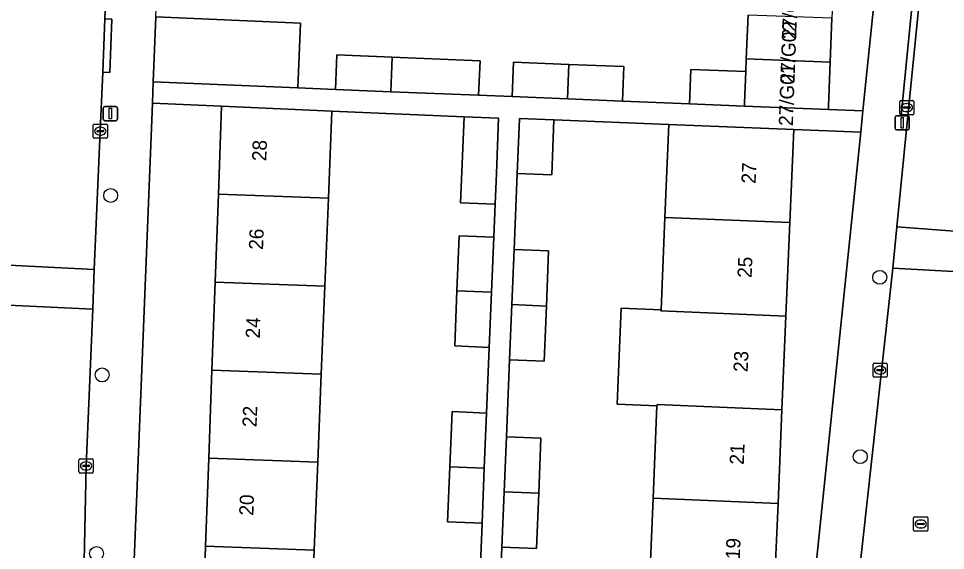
# Model space of a CAD drawing. Extents: x 161354 to 162026, y 386504 to 387460.
# Drawn here: x 161732.9 to 161798.1, y 386751.9 to 386789.3 of the extents above; entities that cross this region are included whole.
import ezdxf

# ---------------------------------------------------------------- set-up
doc = ezdxf.new("R2010")
doc.units = 0
for name, color, linetype in [('IMGEO_Boom', 7, 'Continuous'), ('IMGEO_Erf', 7, 'Continuous'), ('IMGEO_Kolk', 7, 'Continuous'), ('IMGEO_Lichtmast', 7, 'Continuous'), ('IMGEO_Pand', 7, 'Continuous'), ('IMGEO_Pand_nummerreeks', 7, 'Continuous'), ('IMGEO_Rijbaan_lokaal_open', 7, 'Continuous'), ('IMGEO_Rioolput', 7, 'Continuous'), ('IMGEO_Voetpad_open', 7, 'Continuous')]:
    doc.layers.add(name, color=color, linetype=linetype)

msp = doc.modelspace()

# ---------------------------------------------------------------- linework, layer by layer
at = {"layer": 'IMGEO_Boom'}
for centre in [(161739.398, 386776.816), (161793.481, 386771.055), (161738.8, 386764.195), (161792.114, 386758.447), (161738.405, 386751.637)]:
    msp.add_circle(centre, 0.489, dxfattribs=at)
at = {"layer": 'IMGEO_Erf'}
for points in [[(161765.792, 386796.634), (161759.615, 386796.878), (161753.439, 386797.123), (161752.087, 386797.176), (161747.09, 386797.374), (161747.4, 386805.213), (161753.749, 386804.962), (161759.925, 386804.718), (161766.102, 386804.474), (161772.278, 386804.229), (161778.454, 386803.985), (161784.804, 386803.734), (161784.607, 386798.749), (161790.487, 386798.516), (161790.365, 386795.433), (161790.243, 386792.35), (161790.122, 386789.267), (161790, 386786.184), (161789.878, 386783.101), (161789.868, 386782.851), (161792.296, 386782.754), (161794.675, 386805.874)], [(161742.569, 386789.374), (161752.738, 386788.938), (161752.567, 386784.376), (161755.212, 386784.268), (161755.312, 386786.696), (161759.189, 386786.537), (161765.376, 386786.284), (161765.276, 386783.856), (161767.635, 386783.76), (161767.735, 386786.188), (161771.611, 386786.029), (161775.488, 386785.871), (161775.389, 386783.443), (161780.109, 386783.25), (161780.209, 386785.678), (161784.064, 386785.52), (161784.099, 386786.417), (161784.221, 386789.5)], [(161745.992, 386750), (161746.071, 386752.161), (161746.296, 386758.348), (161746.521, 386764.534), (161746.746, 386770.721), (161746.971, 386776.908), (161747.196, 386783.084), (161742.334, 386783.293), (161741.004, 386750)], [(161765.324, 386749.126), (161765.514, 386753.763), (161763.086, 386753.862), (161763.244, 386757.739), (161763.403, 386761.616), (161765.831, 386761.516), (161766.02, 386766.133), (161763.592, 386766.233), (161763.751, 386770.109), (161763.91, 386773.986), (161766.338, 386773.887), (161766.433, 386776.199), (161764.005, 386776.287), (161764.252, 386782.351), (161754.954, 386782.751), (161754.707, 386776.626), (161754.457, 386770.439), (161754.207, 386764.253), (161753.957, 386758.068), (161753.707, 386751.882), (161753.631, 386750)], [(161777.312, 386750), (161777.545, 386755.532), (161777.817, 386762.029), (161775.025, 386762.147), (161775.309, 386768.895), (161778.102, 386768.778), (161778.375, 386775.275), (161778.649, 386781.805), (161770.573, 386782.134), (161770.414, 386778.257), (161767.986, 386778.357), (161767.768, 386773.013), (161770.196, 386772.914), (161770.038, 386769.037), (161769.879, 386765.16), (161767.451, 386765.259), (161767.23, 386759.85), (161769.658, 386759.751), (161769.5, 386755.874), (161769.341, 386751.997), (161766.913, 386752.096), (161766.692, 386746.687)]]:
    msp.add_lwpolyline(points, dxfattribs=at)
msp.add_lwpolyline([(161792.142, 386781.256), (161787.434, 386781.448), (161787.159, 386774.905), (161786.882, 386768.324), (161786.605, 386761.743), (161786.328, 386755.162), (161786.111, 386750), (161786.051, 386748.58), (161785.774, 386741.999), (161785.497, 386735.418), (161785.213, 386728.667), (161786.714, 386728.514), (161788.925, 386750)], close=True, dxfattribs=at)
at = {"layer": 'IMGEO_Kolk'}
for p, q in [((161794.887, 386782.566), (161794.887, 386783.418)), ((161794.962, 386783.492), (161795.814, 386783.492)), ((161795.888, 386783.418), (161795.888, 386782.566)), ((161795.146, 386782.986), (161795.146, 386782.998)), ((161795.584, 386782.949), (161795.186, 386782.949)), ((161795.189, 386783.035), (161795.587, 386783.035)), ((161795.398, 386782.712), (161795.373, 386782.712)), ((161795.375, 386783.272), (161795.4, 386783.272)), ((161795.63, 386782.998), (161795.63, 386782.986)), ((161795.814, 386782.492), (161794.962, 386782.492)), ((161738.169, 386780.908), (161738.169, 386781.76)), ((161738.244, 386781.834), (161739.096, 386781.834)), ((161738.471, 386781.377), (161738.869, 386781.377)), ((161738.657, 386781.614), (161738.682, 386781.614)), ((161739.17, 386781.76), (161739.17, 386780.908)), ((161739.096, 386780.834), (161738.244, 386780.834)), ((161738.428, 386781.328), (161738.428, 386781.34)), ((161738.866, 386781.291), (161738.468, 386781.291)), ((161738.68, 386781.054), (161738.655, 386781.054)), ((161738.912, 386781.34), (161738.912, 386781.328)), ((161793.011, 386764.107), (161793.011, 386764.959)), ((161793.086, 386765.033), (161793.938, 386765.033)), ((161793.27, 386764.527), (161793.27, 386764.539)), ((161793.708, 386764.49), (161793.31, 386764.49)), ((161793.313, 386764.576), (161793.711, 386764.576)), ((161793.499, 386764.813), (161793.524, 386764.813)), ((161793.754, 386764.539), (161793.754, 386764.527)), ((161794.012, 386764.959), (161794.012, 386764.107)), ((161793.938, 386764.033), (161793.086, 386764.033)), ((161793.522, 386764.253), (161793.497, 386764.253)), ((161737.168, 386757.374), (161737.168, 386758.226)), ((161737.243, 386758.3), (161738.095, 386758.3)), ((161737.656, 386758.08), (161737.681, 386758.08)), ((161738.169, 386758.226), (161738.169, 386757.374)), ((161738.095, 386757.3), (161737.243, 386757.3)), ((161737.427, 386757.794), (161737.427, 386757.806)), ((161737.865, 386757.757), (161737.467, 386757.757)), ((161737.47, 386757.843), (161737.868, 386757.843)), ((161737.679, 386757.52), (161737.654, 386757.52)), ((161737.911, 386757.806), (161737.911, 386757.794))]:
    msp.add_line(p, q, dxfattribs=at)
for points in [[(161794.887, 386782.566), (161794.887, 386783.418)], [(161794.962, 386783.492), (161795.814, 386783.492)], [(161795.888, 386783.418), (161795.888, 386782.566)], [(161795.814, 386782.492), (161794.962, 386782.492)], [(161738.169, 386780.908), (161738.169, 386781.76)], [(161738.244, 386781.834), (161739.096, 386781.834)], [(161739.17, 386781.76), (161739.17, 386780.908)], [(161739.096, 386780.834), (161738.244, 386780.834)], [(161793.011, 386764.107), (161793.011, 386764.959)], [(161793.086, 386765.033), (161793.938, 386765.033)], [(161794.012, 386764.959), (161794.012, 386764.107)], [(161793.938, 386764.033), (161793.086, 386764.033)], [(161737.168, 386757.374), (161737.168, 386758.226)], [(161737.243, 386758.3), (161738.095, 386758.3)], [(161738.169, 386758.226), (161738.169, 386757.374)], [(161738.095, 386757.3), (161737.243, 386757.3)]]:
    msp.add_lwpolyline(points, dxfattribs=at)
for centre, radius, start, end in [((161794.964, 386783.416), 0.0765, 91.55205, 178.44795), ((161794.964, 386783.416), 0.0765, 91.55205, 178.44795), ((161795.812, 386783.416), 0.0765, 1.55205, 88.44795), ((161795.812, 386783.416), 0.0765, 1.55205, 88.44795), ((161795.186, 386782.995), 0.0403, 85.87752, 175.75265), ((161795.183, 386782.985), 0.0366, 178.93798, 274.71019), ((161795.587, 386782.992), 0.043, 264.86636, 352.45326), ((161795.591, 386782.997), 0.0386, 1.73085, 96.63898), ((161794.964, 386782.568), 0.0765, 181.55205, 268.44795), ((161794.964, 386782.568), 0.0765, 181.55205, 268.44795), ((161795.812, 386782.568), 0.0765, 271.55205, 358.44795), ((161795.812, 386782.568), 0.0765, 271.55205, 358.44795), ((161738.246, 386781.758), 0.0765, 91.55205, 178.44795), ((161738.246, 386781.758), 0.0765, 91.55205, 178.44795), ((161738.468, 386781.337), 0.0403, 85.87752, 175.75265), ((161738.873, 386781.339), 0.0386, 1.73085, 96.63898), ((161739.094, 386781.758), 0.0765, 1.55205, 88.44795), ((161739.094, 386781.758), 0.0765, 1.55205, 88.44795), ((161738.246, 386780.91), 0.0765, 181.55205, 268.44795), ((161738.246, 386780.91), 0.0765, 181.55205, 268.44795), ((161738.465, 386781.327), 0.0366, 178.93798, 274.71019), ((161738.869, 386781.334), 0.043, 264.86636, 352.45326), ((161739.094, 386780.91), 0.0765, 271.55205, 358.44795), ((161739.094, 386780.91), 0.0765, 271.55205, 358.44795), ((161793.088, 386764.957), 0.0765, 91.55205, 178.44795), ((161793.088, 386764.957), 0.0765, 91.55205, 178.44795), ((161793.31, 386764.536), 0.0403, 85.87752, 175.75265), ((161793.307, 386764.526), 0.0366, 178.93798, 274.71019), ((161793.711, 386764.533), 0.043, 264.86636, 352.45326), ((161793.715, 386764.538), 0.0386, 1.73085, 96.63898), ((161793.936, 386764.957), 0.0765, 1.55205, 88.44795), ((161793.936, 386764.957), 0.0765, 1.55205, 88.44795), ((161793.088, 386764.109), 0.0765, 181.55205, 268.44795), ((161793.088, 386764.109), 0.0765, 181.55205, 268.44795), ((161793.936, 386764.109), 0.0765, 271.55205, 358.44795), ((161793.936, 386764.109), 0.0765, 271.55205, 358.44795), ((161737.245, 386758.224), 0.0765, 91.55205, 178.44795), ((161737.245, 386758.224), 0.0765, 91.55205, 178.44795), ((161738.093, 386758.224), 0.0765, 1.55205, 88.44795), ((161738.093, 386758.224), 0.0765, 1.55205, 88.44795), ((161737.245, 386757.376), 0.0765, 181.55205, 268.44795), ((161737.245, 386757.376), 0.0765, 181.55205, 268.44795), ((161737.467, 386757.803), 0.0403, 85.87752, 175.75265), ((161737.464, 386757.793), 0.0366, 178.93798, 274.71019), ((161737.868, 386757.8), 0.043, 264.86636, 352.45326), ((161737.872, 386757.805), 0.0386, 1.73085, 96.63898), ((161738.093, 386757.376), 0.0765, 271.55205, 358.44795), ((161738.093, 386757.376), 0.0765, 271.55205, 358.44795)]:
    msp.add_arc(centre, radius, start, end, dxfattribs=at)
for centre, major_axis, ratio, start_param, end_param in [((161795.374, 386782.992), (-0.387, 0.002), 0.722429, 4.712389, 7.853982), ((161795.399, 386782.992), (-0.39, 0.002), 0.717154, 1.570796, 4.712389), ((161738.656, 386781.334), (-0.387, 0.002), 0.722429, 4.712389, 7.853982), ((161738.681, 386781.334), (-0.39, 0.002), 0.717154, 1.570796, 4.712389), ((161793.498, 386764.533), (-0.387, 0.002), 0.722429, 4.712389, 7.853982), ((161793.523, 386764.533), (-0.39, 0.002), 0.717154, 1.570796, 4.712389), ((161737.655, 386757.8), (-0.387, 0.002), 0.722429, 4.712389, 7.853982), ((161737.68, 386757.8), (-0.39, 0.002), 0.717154, 1.570796, 4.712389)]:
    msp.add_ellipse(centre, major_axis=major_axis, ratio=ratio, start_param=start_param, end_param=end_param, dxfattribs=at)
at = {"layer": 'IMGEO_Lichtmast'}
for p, q in [((161738.875, 386782.168), (161738.875, 386782.968)), ((161738.875, 386782.968), (161738.875, 386782.168)), ((161738.975, 386783.068), (161739.765, 386783.068)), ((161739.765, 386783.068), (161738.975, 386783.068)), ((161739.865, 386782.968), (161739.865, 386782.168)), ((161739.865, 386782.168), (161739.865, 386782.968)), ((161739.765, 386782.068), (161738.975, 386782.068)), ((161738.975, 386782.068), (161739.765, 386782.068)), ((161794.565, 386781.521), (161794.565, 386782.321)), ((161794.565, 386782.321), (161794.565, 386781.521)), ((161794.665, 386782.421), (161795.455, 386782.421)), ((161795.455, 386782.421), (161794.665, 386782.421)), ((161795.555, 386782.321), (161795.555, 386781.521)), ((161795.555, 386781.521), (161795.555, 386782.321)), ((161795.455, 386781.421), (161794.665, 386781.421)), ((161794.665, 386781.421), (161795.455, 386781.421))]:
    msp.add_line(p, q, dxfattribs=at)
for points in [[(161739.295, 386782.943), (161739.445, 386782.943), (161739.445, 386782.193), (161739.295, 386782.193), (161739.295, 386782.943)], [(161794.985, 386782.296), (161795.135, 386782.296), (161795.135, 386781.546), (161794.985, 386781.546), (161794.985, 386782.296)]]:
    msp.add_lwpolyline(points, dxfattribs=at)
for centre, start, end in [((161738.975, 386782.968), 90, 180), ((161738.975, 386782.968), 90, 180), ((161739.765, 386782.968), 0, 90), ((161739.765, 386782.968), 360, 90), ((161738.975, 386782.168), 180, 270), ((161738.975, 386782.168), 180, 270), ((161739.765, 386782.168), 270, 0), ((161739.765, 386782.168), 270, 0), ((161794.665, 386782.321), 90, 180), ((161794.665, 386782.321), 90, 180), ((161795.455, 386782.321), 0, 90), ((161795.455, 386782.321), 360, 90), ((161794.665, 386781.521), 180, 270), ((161794.665, 386781.521), 180, 270), ((161795.455, 386781.521), 270, 0), ((161795.455, 386781.521), 270, 0)]:
    msp.add_arc(centre, 0.1, start, end, dxfattribs=at)
at = {"layer": 'IMGEO_Pand'}
for points in [[(161752.738, 386788.938), (161742.569, 386789.374), (161742.388, 386784.792), (161752.567, 386784.376)], [(161790, 386786.184), (161790.122, 386789.267), (161784.221, 386789.5), (161784.099, 386786.417)], [(161759.189, 386786.537), (161755.312, 386786.696), (161755.212, 386784.268), (161759.089, 386784.109)], [(161759.189, 386786.537), (161759.089, 386784.109), (161765.276, 386783.856), (161765.376, 386786.284)], [(161771.611, 386786.029), (161767.735, 386786.188), (161767.635, 386783.76), (161771.512, 386783.601)], [(161771.611, 386786.029), (161771.512, 386783.601), (161775.389, 386783.443), (161775.488, 386785.871)], [(161790, 386786.184), (161784.099, 386786.417), (161784.064, 386785.52), (161783.977, 386783.334), (161783.967, 386783.092), (161789.868, 386782.851), (161789.878, 386783.101)], [(161784.064, 386785.52), (161780.209, 386785.678), (161780.109, 386783.25), (161783.967, 386783.092), (161783.977, 386783.334)], [(161754.954, 386782.751), (161747.196, 386783.084), (161746.971, 386776.908), (161754.707, 386776.626)], [(161766.68, 386782.247), (161764.252, 386782.351), (161764.005, 386776.287), (161766.433, 386776.199), (161766.521, 386778.354)], [(161770.573, 386782.134), (161768.145, 386782.233), (161768.143, 386782.188), (161767.986, 386778.357), (161770.414, 386778.257)], [(161787.434, 386781.448), (161778.649, 386781.805), (161778.375, 386775.275), (161787.159, 386774.905)], [(161746.971, 386776.908), (161746.746, 386770.721), (161754.457, 386770.439), (161754.707, 386776.626)], [(161787.159, 386774.905), (161778.375, 386775.275), (161778.102, 386768.778), (161778.098, 386768.694), (161786.882, 386768.324)], [(161766.338, 386773.887), (161763.91, 386773.986), (161763.751, 386770.109), (161766.179, 386770.01)], [(161767.768, 386773.013), (161767.61, 386769.136), (161770.038, 386769.037), (161770.196, 386772.914)], [(161754.207, 386764.253), (161754.457, 386770.439), (161746.746, 386770.721), (161746.521, 386764.534)], [(161766.179, 386770.01), (161763.751, 386770.109), (161763.592, 386766.233), (161766.02, 386766.133)], [(161770.038, 386769.037), (161767.61, 386769.136), (161767.451, 386765.259), (161769.879, 386765.16)], [(161786.882, 386768.324), (161778.098, 386768.694), (161778.102, 386768.778), (161775.309, 386768.895), (161775.025, 386762.147), (161777.817, 386762.029), (161777.821, 386762.113), (161786.605, 386761.743)], [(161746.521, 386764.534), (161746.296, 386758.348), (161753.957, 386758.068), (161754.207, 386764.253)], [(161786.605, 386761.743), (161777.821, 386762.113), (161777.817, 386762.029), (161777.545, 386755.532), (161786.328, 386755.162)], [(161765.831, 386761.516), (161763.403, 386761.616), (161763.244, 386757.739), (161765.672, 386757.64)], [(161767.23, 386759.85), (161767.072, 386755.973), (161769.5, 386755.874), (161769.658, 386759.751)], [(161753.707, 386751.882), (161753.957, 386758.068), (161746.296, 386758.348), (161746.071, 386752.161)], [(161765.672, 386757.64), (161763.244, 386757.739), (161763.086, 386753.862), (161765.514, 386753.763)], [(161769.5, 386755.874), (161767.072, 386755.973), (161766.913, 386752.096), (161769.341, 386751.997)], [(161786.051, 386748.58), (161786.111, 386750), (161786.328, 386755.162), (161777.545, 386755.532), (161777.312, 386750), (161777.268, 386748.95)], [(161753.457, 386745.696), (161753.631, 386750), (161753.707, 386751.882), (161746.071, 386752.161), (161745.992, 386750), (161745.845, 386745.974)]]:
    msp.add_lwpolyline(points, close=True, dxfattribs=at)
at = {"layer": 'IMGEO_Rijbaan_lokaal_open'}
for points in [[(161810.449, 386859.714), (161810.529, 386860.484), (161811.96, 386874.964), (161812.005, 386875.25), (161805.039, 386875.878), (161801.767, 386845.595), (161800.039, 386827.337), (161799.609, 386822.721), (161799.571, 386822.084), (161797.768, 386804.716), (161797.697, 386804.314), (161797.098, 386798.789), (161795.448, 386782.404), (161794.685, 386774.619), (161801.521, 386774.099), (161802.439, 386783.05), (161803.985, 386798.113), (161805.206, 386810.004), (161805.846, 386816.239), (161807.365, 386830.715), (161809.036, 386846.425), (161809.202, 386847.985)], [(161738.987, 386789.237), (161739.507, 386801.947), (161739.723, 386805.754), (161732.672, 386805.988), (161731.994, 386788.705), (161731.85, 386785.082), (161731.746, 386782.581), (161731.292, 386771.956), (161738.237, 386771.602), (161738.664, 386781.334), (161738.834, 386785.48)], [(161801.521, 386774.099), (161794.685, 386774.619), (161794.403, 386771.693), (161801.237, 386771.333)], [(161731.292, 386771.956), (161731.175, 386769.153), (161738.131, 386768.811), (161738.237, 386771.602)], [(161798.13, 386741.172), (161798.266, 386742.482), (161799.047, 386750), (161799.477, 386754.186), (161801.237, 386771.333), (161794.403, 386771.693), (161792.01, 386750), (161789.803, 386728.701), (161788.482, 386715.948), (161786.624, 386698.019), (161784.434, 386674.841), (161784.094, 386671.248), (161782.825, 386657.818), (161789.606, 386657.165), (161792.334, 386684.195), (161794.081, 386700.543), (161794.13, 386700.862), (161794.961, 386709.575), (161796.448, 386724.974), (161796.589, 386726.34)], [(161737.515, 386750), (161737.664, 386757.8), (161738.131, 386768.811), (161731.175, 386769.153), (161730.711, 386758.025), (161730.697, 386753.106), (161730.304, 386743.254), (161730.096, 386738.148), (161729.261, 386717.657), (161729, 386711.269), (161735.937, 386711.052), (161736.362, 386721.528), (161736.628, 386728.094)]]:
    msp.add_lwpolyline(points, close=True, dxfattribs=at)
at = {"layer": 'IMGEO_Rioolput'}
for p, q in [((161795.867, 386753.289), (161795.867, 386754.141)), ((161795.942, 386754.215), (161796.794, 386754.215)), ((161796.355, 386753.995), (161796.38, 386753.995)), ((161796.868, 386754.141), (161796.868, 386753.289)), ((161796.126, 386753.709), (161796.126, 386753.721)), ((161796.564, 386753.672), (161796.166, 386753.672)), ((161796.169, 386753.758), (161796.567, 386753.758)), ((161796.378, 386753.435), (161796.353, 386753.435)), ((161796.61, 386753.721), (161796.61, 386753.709)), ((161796.794, 386753.215), (161795.942, 386753.215))]:
    msp.add_line(p, q, dxfattribs=at)
for points in [[(161795.867, 386753.289), (161795.867, 386754.141)], [(161795.942, 386754.215), (161796.794, 386754.215)], [(161796.868, 386754.141), (161796.868, 386753.289)], [(161796.794, 386753.215), (161795.942, 386753.215)]]:
    msp.add_lwpolyline(points, dxfattribs=at)
for centre, radius, start, end in [((161795.944, 386754.139), 0.0765, 91.55205, 178.44795), ((161795.944, 386754.139), 0.0765, 91.55205, 178.44795), ((161796.792, 386754.139), 0.0765, 1.55205, 88.44795), ((161796.792, 386754.139), 0.0765, 1.55205, 88.44795), ((161796.166, 386753.718), 0.0403, 85.87752, 175.75265), ((161796.163, 386753.708), 0.0366, 178.93798, 274.71019), ((161796.567, 386753.715), 0.043, 264.86636, 352.45326), ((161796.571, 386753.72), 0.0386, 1.73085, 96.63898), ((161795.944, 386753.291), 0.0765, 181.55205, 268.44795), ((161795.944, 386753.291), 0.0765, 181.55205, 268.44795), ((161796.792, 386753.291), 0.0765, 271.55205, 358.44795), ((161796.792, 386753.291), 0.0765, 271.55205, 358.44795)]:
    msp.add_arc(centre, radius, start, end, dxfattribs=at)
for centre, major_axis, ratio, start_param, end_param in [((161796.354, 386753.715), (-0.387, 0.002), 0.722429, 4.712389, 7.853982), ((161796.379, 386753.715), (-0.39, 0.002), 0.717154, 1.570796, 4.712389)]:
    msp.add_ellipse(centre, major_axis=major_axis, ratio=ratio, start_param=start_param, end_param=end_param, dxfattribs=at)
at = {"layer": 'IMGEO_Voetpad_open'}
for points in [[(161796.099, 386809.009), (161794.675, 386805.874), (161792.296, 386782.754), (161792.142, 386781.256), (161788.925, 386750), (161786.714, 386728.514), (161789.258, 386728.258), (161789.309, 386728.747), (161789.803, 386728.701), (161792.01, 386750), (161794.403, 386771.693)], [(161741.004, 386750), (161742.334, 386783.293), (161742.388, 386784.792), (161742.569, 386789.374), (161743.05, 386801.465), (161743.228, 386805.954), (161743.265, 386806.873), (161739.86, 386806.986), (161739.723, 386805.754), (161739.507, 386801.947), (161738.987, 386789.237), (161739.488, 386789.217), (161739.334, 386785.46), (161738.834, 386785.48), (161738.664, 386781.334), (161738.237, 386771.602), (161738.131, 386768.811), (161737.664, 386757.8), (161737.515, 386750)], [(161794.403, 386771.693), (161794.685, 386774.619), (161795.448, 386782.404), (161794.978, 386782.445), (161796.607, 386798.831), (161797.098, 386798.789), (161797.697, 386804.314)], [(161766.692, 386746.687), (161766.913, 386752.096), (161767.072, 386755.973), (161767.23, 386759.85), (161767.451, 386765.259), (161767.61, 386769.136), (161767.768, 386773.013), (161767.986, 386778.357), (161768.143, 386782.188), (161768.145, 386782.233), (161770.573, 386782.134), (161778.649, 386781.805), (161787.434, 386781.448), (161792.142, 386781.256), (161792.296, 386782.754), (161789.868, 386782.851), (161783.967, 386783.092), (161780.109, 386783.25), (161775.389, 386783.443), (161771.512, 386783.601), (161767.635, 386783.76), (161765.276, 386783.856), (161759.089, 386784.109), (161755.212, 386784.268), (161752.567, 386784.376), (161742.388, 386784.792), (161742.334, 386783.293), (161747.196, 386783.084), (161754.954, 386782.751), (161764.252, 386782.351), (161766.68, 386782.247), (161766.521, 386778.354), (161766.433, 386776.199), (161766.338, 386773.887), (161766.179, 386770.01), (161766.02, 386766.133), (161765.831, 386761.516), (161765.672, 386757.64), (161765.514, 386753.763), (161765.324, 386749.126)]]:
    msp.add_lwpolyline(points, dxfattribs=at)
for points in [[(161797.098, 386798.789), (161796.607, 386798.831), (161794.978, 386782.445), (161795.448, 386782.404)], [(161738.987, 386789.237), (161738.834, 386785.48), (161739.334, 386785.46), (161739.488, 386789.217)]]:
    msp.add_lwpolyline(points, close=True, dxfattribs=at)

# ---------------------------------------------------------------- texts
at = {"layer": 'IMGEO_Pand_nummerreeks'}
for s, rotation, p in [('27/G03', 87.88601, (161787.597, 386787.78)), ('27/G02', 87.88601, (161787.482, 386784.669)), ('27/G01', 87.886, (161787.372, 386781.682)), ('28', 87.91464, (161750.337, 386779.212)), ('27', 87.58806, (161784.75, 386777.626)), ('26', 87.91466, (161750.111, 386772.978)), ('25', 87.58806, (161784.471, 386771.002)), ('24', 87.91466, (161749.884, 386766.748)), ('23', 87.58806, (161784.193, 386764.378)), ('22', 87.91466, (161749.657, 386760.514)), ('21', 87.58806, (161783.919, 386757.867)), ('20', 87.91466, (161749.43, 386754.289)), ('19', 87.59027, (161783.64, 386751.222))]:
    msp.add_text(s, height=1, rotation=rotation, dxfattribs=at).set_placement(p)

doc.saveas('drawing.dxf')
